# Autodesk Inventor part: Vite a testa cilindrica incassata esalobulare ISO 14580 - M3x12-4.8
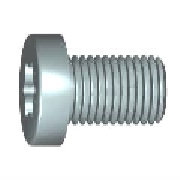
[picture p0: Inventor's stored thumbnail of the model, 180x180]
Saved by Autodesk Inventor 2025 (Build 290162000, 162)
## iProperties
Created: 2024-01
Part Number: Vite a testa cilindrica incassata esalobulare ISO 14580 - M3x12-4.8
Material: Acciaio
Description: ISO 14580 - Viti a testa cilindrica incassata esalobulare - Seconda edizione
Document SubType Name: Modeling
Standard: 14580
Designer: Ryzen5700u
Standards Organization: ISO
Language: it-IT
Size Designation: M3x12-4.8
Categories: <MemberInstance><Categories><Category DisplayName="Elementi di fissaggio" InternalName="e4da775c-781d-43d5-af7c-5136215cf5a6" Mnemonic="FSTN"><Category DisplayN
Density: 7.85 g/cm^3
Appearance: Lamiera
IsCustomPart: 0
Author: Ryzen5700u
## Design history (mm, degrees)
revolve "Revolution1" stored, may be unused: angle "d4" = 90 deg
thread "Thread1" dims "d6" = 12 (= b), "d7" = 0
sketch "Sketch2" dims "d21" = 2.8 (= A_)
  geometry: L1 (-0.849, -0.49)-(-1.4, 0); L2 (0, 0)-(-0.849, -0.49); L3 (0, 0)-(-0.849, 0.49); L4 (-4.144, 0)-(4.144, 0) reference; L5 (-1.4, 0)-(-0.849, 0.49); A1 r 0.98 centre (0, 0) between (-0.849, -0.49) and (-0.849, 0.49); 2 further points
  constraints: 8 end point, 2 coincident, 2 point on circle, 1 centre point, 1 horizontal alignment, 1 point on line, 2 other
  dimensions: "d19" = 60 deg angle of L3 L2; "d20" = 30 deg angle of L3 L4 (= 0.5 x d19); "d26" = 1.96 diameter of A1 (= 0.7 x d21)
extrude "Extrusion1" cut sketch "Sketch2" distance "d27" = 1.27 (= t); taper "d28" = 0 deg
pattern_circular "Circular Pattern1" dims angle "d30" = 360 deg
fillet "Fillet2" dims "d32" = 0.3 (= v)
fillet "Fillet3" dims "d33" = 0.3 (= v)
fillet "Fillet5" dims "d35" = 0.1 (= r)
chamfer "Chamfer2" distance "d36" = 0.3 (= v); stored, may be unused: second distance "d37" = 2, angle "d38" = 45 deg
body "Solid1"
sketch "Sketch1"
  geometry: L1 (0, 0)-(12, 0); L2 (12, 0)-(12, 1.5); L3 (12, 1.5)-(0, 1.5); L4 (0, 1.5)-(0, 0); L5 (0, 0)-(-2.4, 0); L6 (-2.4, 0)-(-2.4, 2.75); L7 (-2.4, 2.75)-(0, 2.96); L8 (0, 2.96)-(0, 0)
  constraints: 16 end point, 3 parallel, 2 horizontal, 2 perpendicular
  dimensions: "d0" = 3 diameter of L3 L1 (= d); "d3" = 12 distance of L2.end L3.end (= l_); "d46" = 85 deg angle of L8 L7; "d47" = 2.4 distance between parallel lines of L8 L6 (= k); "d49" = 5.5 diameter of L6.end L1 (= dk)
other parameters: "A_" = 2.8 [user parameter; used in 1 equation term], "d" = 3 [user parameter; used in 2 equation terms], "dk" = 5.5 [user parameter; used in 1 equation term], "k" = 2.4 [user parameter; used in 1 equation term], "l_" = 12 [user parameter; used in 2 equation terms], "lg" = 0 [user parameter; used in 1 equation term], "t" = 1.27 [user parameter; used in 1 equation term], "w" = 0.55 [user parameter], "v" = 0.3 [user parameter; used in 3 equation terms], "r" = 0.1 [user parameter; used in 1 equation term], "da" = 2.6 [user parameter], "ds_" = 3 (= d) [user parameter], "ls" = 0 [user parameter], "b" = 12 (= l_ - lg) [user parameter; used in 1 equation term], "d42" = 0, "d43" = 0, "d44" = 0, "p" = 0.5 [user parameter]
